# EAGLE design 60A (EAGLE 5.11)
PID: 626
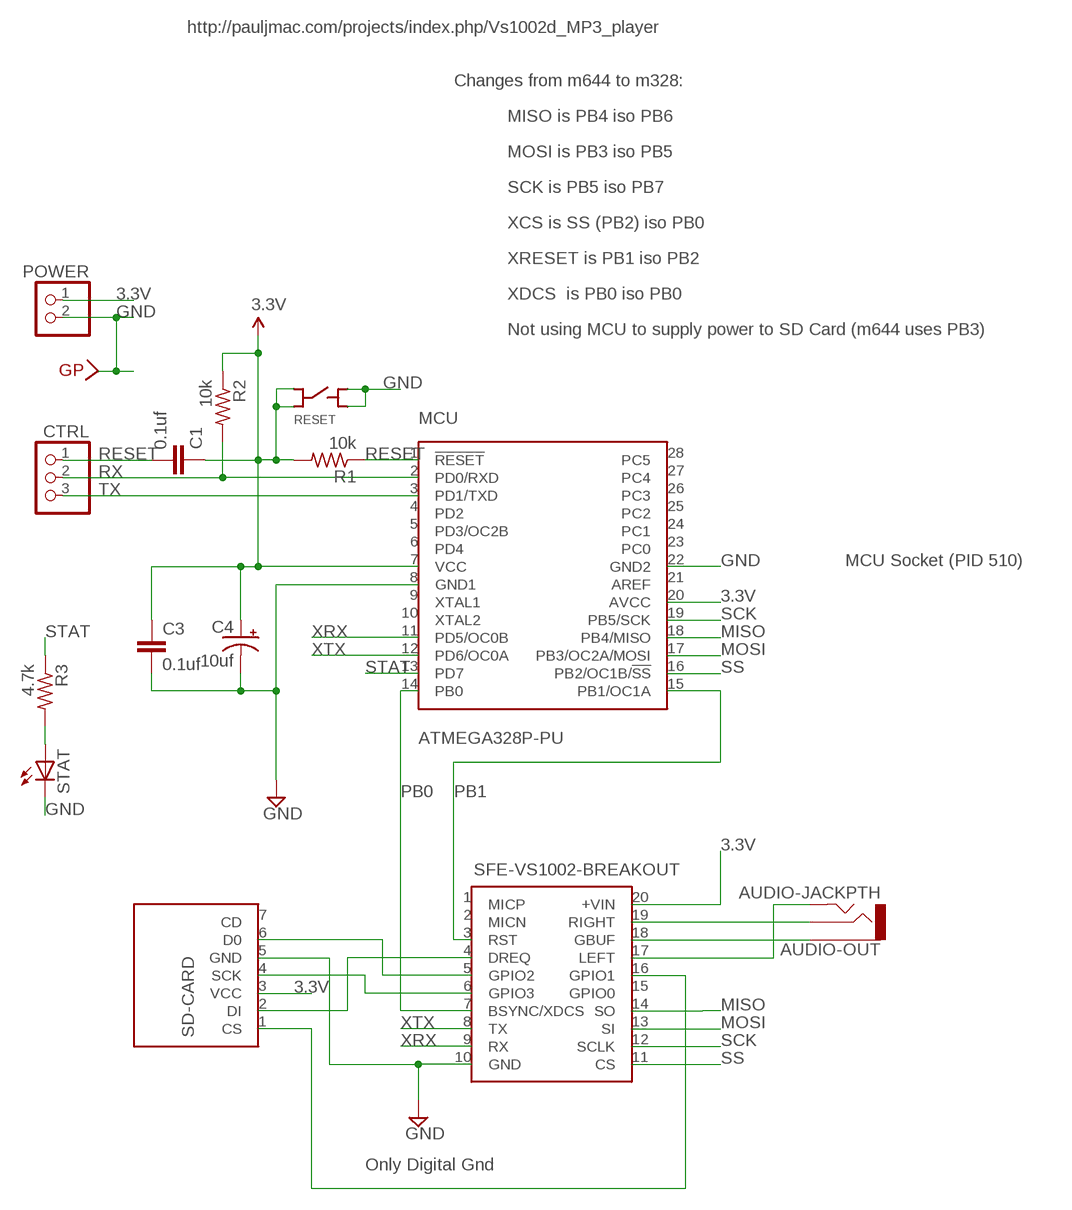
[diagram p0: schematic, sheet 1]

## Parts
AUDIO-OUT  AUDIO-JACKPTH  [AUDIO-JACK]
C1  0.1uf  C-EUC1206  [C1206]
C3  0.1uf  C-EUC1206  [C1206]
C4  10uf  CPOL-USE2-4  [E2-4]
CTRL  PINHD-1X3  [1X03]
GP  WIREPAD-SMD-SMALL-NAMED  [WIREPAD-SMD-SMALL]
MCU  ATMEGA328P-PU  [DIL28-3]
POWER  PINHD-1X2  [1X02]
R1  10k  R-US_M0805  [M0805]
R2  10k  R-US_R0805  [R0805]
R3  4.7k  R-US_R1206  [R1206]
RESET  SFE-PUSHBUTTON-SWITCH  [SFE-PUSHBUTTON-SWITCH]
SD-CARD  SFE-MICRO-SD-CARD-BREAKOUT  [SFE-MICRO-SD-CARD-BREAKOUT]
SFE-VS1002-BREAKOUT  SFE-VS1002-BREAKOUT  [SFE-VS1002-BREAKOUT]
STAT  LED5MM  [LED5MM]

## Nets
3.3V: C1.1 C3.1 C4.+ MCU.7(VCC) MCU.20(AVCC) POWER.1 R1.2 R2.1 RESET.C@1(C) RESET.C@2(C) SD-CARD.3(VCC) SFE-VS1002-BREAKOUT.20(+VIN)
GND: C3.2 C4.- GP.1 MCU.8(GND1) MCU.22(GND2) POWER.2 RESET.O@1(O) RESET.O@2(O) SD-CARD.5(GND) SFE-VS1002-BREAKOUT.10(GND) STAT.K(C)
MISO: MCU.18(PB4/MISO) SFE-VS1002-BREAKOUT.14(SO)
MOSI: MCU.17(PB3/OC2A/MOSI) SFE-VS1002-BREAKOUT.13(SI)
N$1: R3.2 STAT.A
N$2: AUDIO-OUT.1 SFE-VS1002-BREAKOUT.18(GBUF)
N$3: AUDIO-OUT.2 SFE-VS1002-BREAKOUT.19(RIGHT)
N$4: SD-CARD.2(DI) SFE-VS1002-BREAKOUT.4(DREQ)
N$5: SD-CARD.4(SCK) SFE-VS1002-BREAKOUT.6(GPIO3)
N$6: SD-CARD.6(D0) SFE-VS1002-BREAKOUT.5(GPIO2)
N$7: SD-CARD.1(CS) SFE-VS1002-BREAKOUT.16(GPIO1)
N$8: AUDIO-OUT.5 SFE-VS1002-BREAKOUT.17(LEFT)
PB0: MCU.14(PB0) SFE-VS1002-BREAKOUT.7(BSYNC/XDCS)
PB1: MCU.15(PB1/OC1A) SFE-VS1002-BREAKOUT.3(RST)
RESET: C1.2 CTRL.1 MCU.1(!RESET) R1.1
RX: CTRL.2 MCU.2(PD0/RXD) R2.2
SCK: MCU.19(PB5/SCK) SFE-VS1002-BREAKOUT.12(SCLK)
SS: MCU.16(PB2/OC1B/!SS) SFE-VS1002-BREAKOUT.11(CS)
STAT: MCU.13(PD7) R3.1
TX: CTRL.3 MCU.3(PD1/TXD)
XRX: MCU.11(PD5/OC0B) SFE-VS1002-BREAKOUT.9(RX)
XTX: MCU.12(PD6/OC0A) SFE-VS1002-BREAKOUT.8(TX)
Unconnected: MCU.4(PD2) MCU.5(PD3/OC2B) MCU.6(PD4) MCU.9(XTAL1) MCU.10(XTAL2) MCU.21(AREF) MCU.23(PC0) MCU.24(PC1) MCU.25(PC2) MCU.26(PC3) MCU.27(PC4) MCU.28(PC5) SD-CARD.7(CD) SFE-VS1002-BREAKOUT.1(MICP) SFE-VS1002-BREAKOUT.2(MICN) SFE-VS1002-BREAKOUT.15(GPIO0)

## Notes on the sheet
- http://pauljmac.com/projects/index.php/Vs1002d_MP3_player
- Changes from m644 to m328:
- MISO is PB4 iso PB6
- MOSI is PB3 iso PB5
- SCK is PB5 iso PB7
- XCS is SS (PB2) iso PB0
- XRESET is PB1 iso PB2
- XDCS  is PB0 iso PB0
- Not using MCU to supply power to SD Card (m644 uses PB3)
- MCU Socket (PID 510)
- Only Digital Gnd

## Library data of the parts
AUDIO-OUT = SparkFun:AUDIO-JACK: 3.5mm Audio Jack Simple 3.5mm common PCB mount audio jack. SKU: PRT-08032
C1 C3 = rcl:C-EU: CAPACITOR, European symbol
C4 = rcl:CPOL-US: POLARIZED CAPACITOR, American symbol
CTRL = pinhead:PINHD-1X3: PIN HEADER
GP = trl:WIREPAD-SMD-SMALL-NAMED
MCU = trl:ATMEGA328P-PU
POWER = pinhead:PINHD-1X2: PIN HEADER
R1-R3 = resistor:R-US_: RESISTOR, American symbol
RESET = trl:SFE-PUSHBUTTON-SWITCH
SD-CARD = trl:SFE-MICRO-SD-CARD-BREAKOUT
SFE-VS1002-BREAKOUT = trl:SFE-VS1002-BREAKOUT
STAT = led:LED: LED

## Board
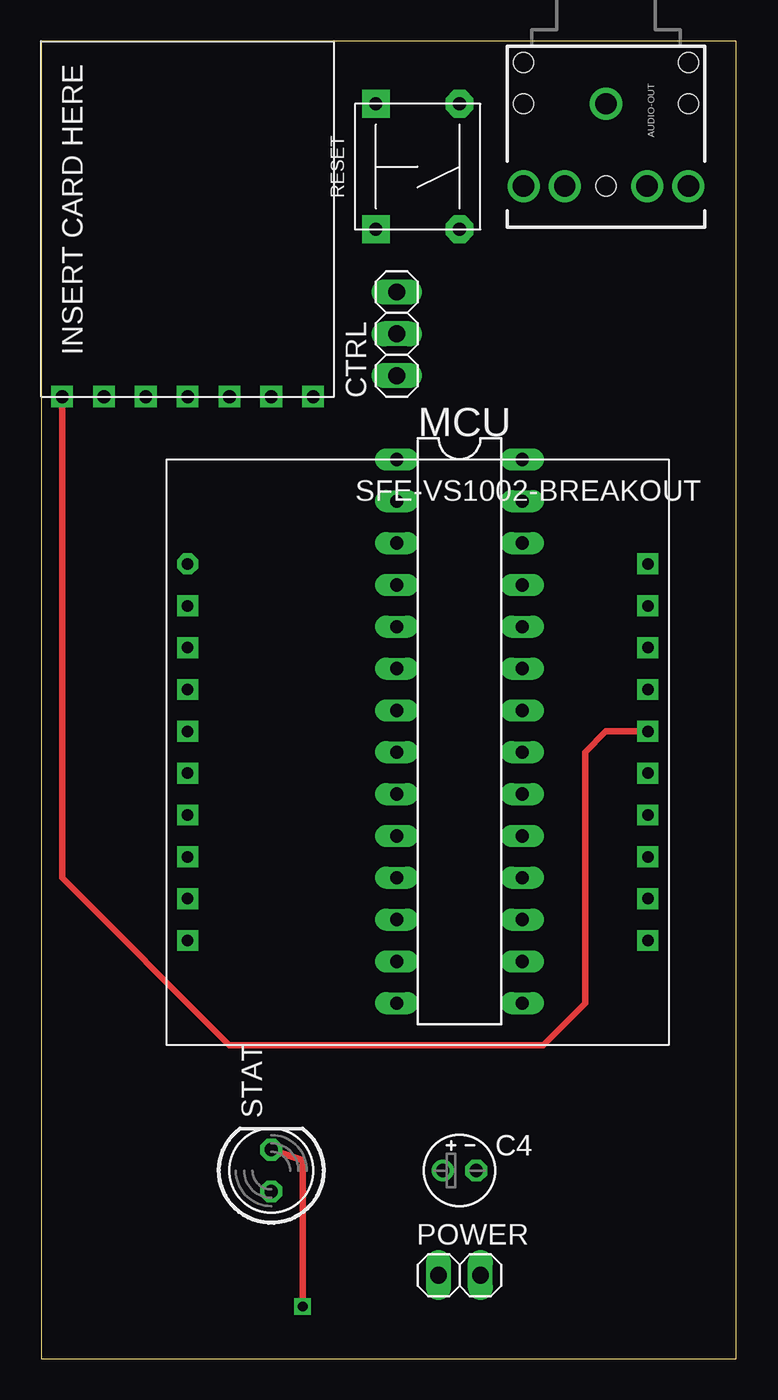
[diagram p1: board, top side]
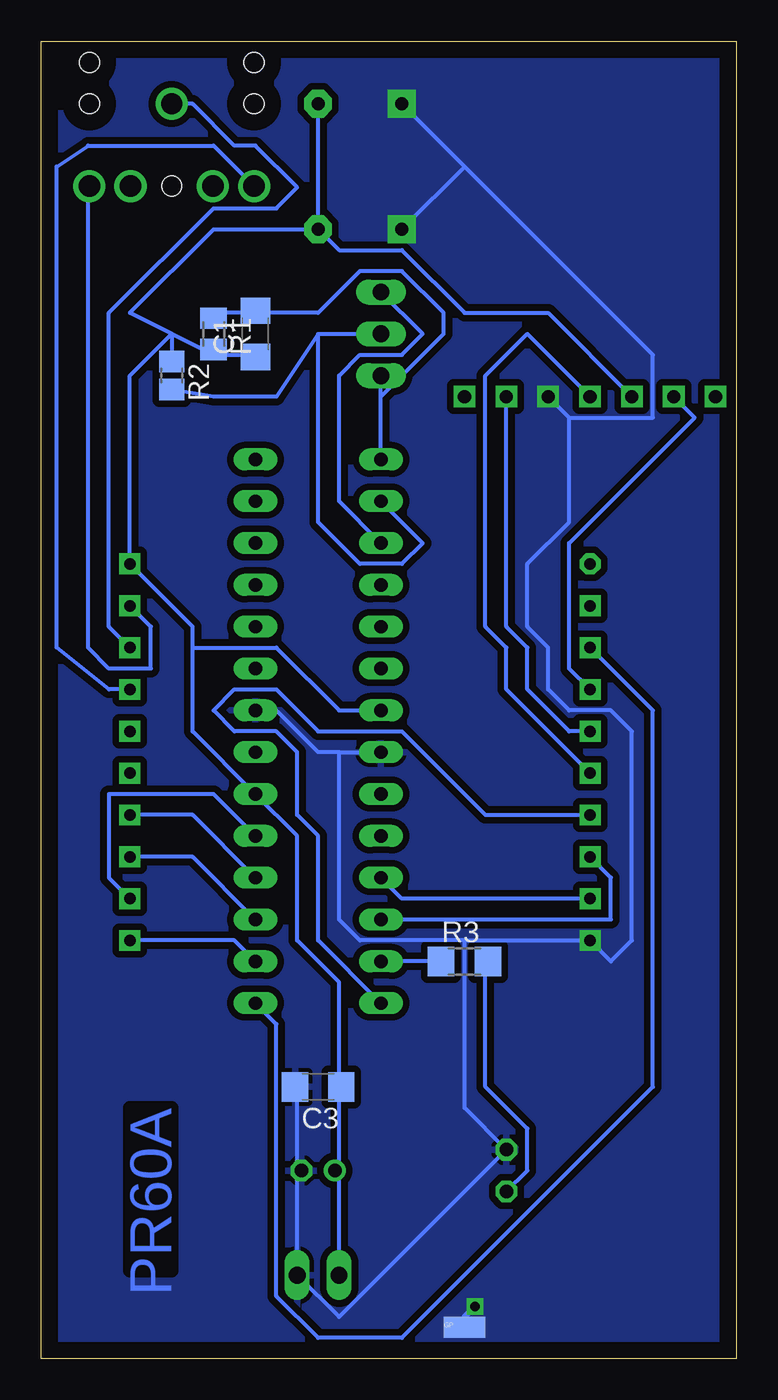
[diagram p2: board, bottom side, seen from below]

Size 42.22 x 80 mm. Coordinates in mm from the lower left corner, seen from the top.
Outline: 0,0 42.22,0 42.22,80 0,80 0,0
Copper layers (1*16): Top 0.035mm / dielectric 1.5mm / Bottom 0.035mm
Design rules "default": minimum track width 10mil, minimum drill 24mil, track to track 8mil, track to pad 8mil, pad to pad 8mil, via to via 8mil, smd to smd 8mil, copper to edge 40mil, drill to drill 8mil, minimum pad ring 10mil, minimum via ring 8mil, stop-mask expansion 4mil, vias tented up to drill 0mil, thermal gap 10mil

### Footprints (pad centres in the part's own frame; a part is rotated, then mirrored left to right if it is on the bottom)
AUDIO-JACK = drill 1.3 round: 1 0,0; 2 5,5; 3 5,2.5; 4 5,-2.5; 5 5,-5 | hole 1.2: 0,5; -2.5,5; -2.5,-5; 0,-5; 5,0
C1206 = smd 1.6 x 1.8: 1 -1.4,0; 2 1.4,0
E2-4 = drill 0.813 pad 1.27 round: + -1.016,0 | drill 0.813 pad 1.27 octagon: - 1.016,0
1X03 = drill 1.016 long: 1 -2.54,0; 2 0,0; 3 2.54,0
WIREPAD-SMD-SMALL = smd 2.54 x 1.27: 1 0,0
DIL28-3 = drill 0.813 long: 1 -16.51,-3.81; 2 -13.97,-3.81; 3 -11.43,-3.81; 4 -8.89,-3.81; 5 -6.35,-3.81; 6 -3.81,-3.81; 7 -1.27,-3.81; 8 1.27,-3.81; 9 3.81,-3.81; 10 6.35,-3.81; 11 8.89,-3.81; 12 11.43,-3.81; 13 13.97,-3.81; 14 16.51,-3.81; 15 16.51,3.81; 16 13.97,3.81; 17 11.43,3.81; 18 8.89,3.81; 19 6.35,3.81; 20 3.81,3.81; 21 1.27,3.81; 22 -1.27,3.81; 23 -3.81,3.81; 24 -6.35,3.81; 25 -8.89,3.81; 26 -11.43,3.81; 27 -13.97,3.81; 28 -16.51,3.81
1X02 = drill 1.016 long: 1 -1.27,0; 2 1.27,0
M0805 = smd 1.3 x 1.6: 1 -0.95,0; 2 0.95,0
R0805 = smd 1.3 x 1.5: 1 -0.85,0; 2 0.85,0
R1206 = smd 1.6 x 1.803: 1 -1.422,0; 2 1.422,0
SFE-PUSHBUTTON-SWITCH = drill 0.8 pad 1.676 octagon: C@1 -3.81,-2.54; C@2 3.81,-2.54 | drill 0.8 pad 1.676 square: O@1 -3.81,2.54; O@2 3.81,2.54
SFE-MICRO-SD-CARD-BREAKOUT = drill 0.8 square: 1 -7.62,-10.16; 2 -5.08,-10.16; 3 -2.54,-10.16; 4 0,-10.16; 5 2.54,-10.16; 6 5.08,-10.16; 7 7.62,-10.16
SFE-VS1002-BREAKOUT = drill 0.7 pad 1.27 octagon: 1 -13.97,11.43 | drill 0.7 pad 1.27 square: 2 -13.97,8.89; 3 -13.97,6.35; 4 -13.97,3.81; 5 -13.97,1.27; 6 -13.97,-1.27; 7 -13.97,-3.81; 8 -13.97,-6.35; 9 -13.97,-8.89; 10 -13.97,-11.43; 11 13.97,-11.43; 12 13.97,-8.89; 13 13.97,-6.35; 14 13.97,-3.81; 15 13.97,-1.27; 16 13.97,1.27; 17 13.97,3.81; 18 13.97,6.35; 19 13.97,8.89; 20 13.97,11.43
LED5MM = drill 0.813 octagon: A -1.27,0; K 1.27,0

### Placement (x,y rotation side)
AUDIO-OUT  34.29,76.2 270 top
C1  29.21,62.23 90 bottom
C3  25.4,16.51 180 bottom
C4  25.4,11.43 0 top
CTRL  21.59,62.23 90 top
GP  16.51,1.91 0 bottom
MCU  25.4,38.1 270 top
POWER  25.4,5.08 0 top
R1  31.75,62.23 270 bottom
R2  34.29,59.69 270 bottom
R3  16.51,24.13 0 bottom
RESET  22.86,72.39 90 top
SD-CARD  8.89,68.58 0 top
SFE-VS1002-BREAKOUT  22.86,36.83 0 top
STAT  13.97,11.43 90 top

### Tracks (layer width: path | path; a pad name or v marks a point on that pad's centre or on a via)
3.3V
  Bottom 0.254: SD-CARD.3 11.43,63.5 16.51,63.5 20.32,67.31 24.13,67.31 RESET.C@1 | RESET.C@1 RESET.C@2 | 24.13,11.43 24.13,16.51 | POWER.1 24.13,11.43 | 24.13,11.43 C4.+ | 31.75,60.96 29.21,60.96 C1.1 | 34.29,62.23 31.75,60.96 | 31.75,60.96 R1.2 | 34.29,62.23 36.83,59.69 SFE-VS1002-BREAKOUT.20 33.02,44.45 33.02,43.18 | 33.02,43.18 33.02,38.1 MCU.20 26.67,31.75 26.67,25.4 24.13,22.86 24.13,16.51 | MCU.7 24.13,39.37 27.94,43.18 33.02,43.18 | 24.13,16.51 C3.1 | RESET.C@1 31.75,68.58 36.83,63.5 34.29,62.23 | 34.29,62.23 R2.1
GND  (via drill 0.6)
  Top 0.406: v15.88,3.17 15.88,12.06 STAT.K
  Bottom 0.254: 10.16,57.15 SD-CARD.5 | 10.16,57.15 5.08,57.15 5.08,60.96 16.51,72.39 | 16.51,72.39 RESET.O@2 | 16.51,72.39 RESET.O@1 | 26.67,11.43 26.67,16.51 C3.2 | 26.67,11.43 POWER.2 24.13,2.54 STAT.K 16.51,15.24 16.51,25.4 | 26.67,11.43 C4.- | 24.13,36.83 25.4,36.83 27.94,39.37 MCU.22 | 24.13,36.83 MCU.8 | 16.51,25.4 SFE-VS1002-BREAKOUT.10 7.62,24.13 6.35,25.4 6.35,38.1 7.62,39.37 10.16,39.37 11.43,40.64 11.43,43.18 12.7,44.45 12.7,48.26 10.16,50.8 10.16,57.15 | 24.13,36.83 24.13,26.67 22.86,25.4 16.51,25.4
  Bottom 0.406: GP.1 16.51,2.54 v15.88,3.17
  pour Bottom (isolate 0.406): 0,80.01 41.91,80.01 41.91,78.74 41.91,0 0,0
MISO
  Bottom 0.254: SFE-VS1002-BREAKOUT.14 33.02,33.02 MCU.18
MOSI
  Bottom 0.254: SFE-VS1002-BREAKOUT.13 33.02,30.48 MCU.17
N$1
  Bottom 0.254: STAT.A 12.7,11.43 12.7,13.97 15.24,16.51 15.24,24.13 R3.2
N$2
  Bottom 0.254: SFE-VS1002-BREAKOUT.18 38.1,44.45 38.1,63.5 31.75,69.85 27.94,69.85 26.67,71.12 29.21,73.66 30.48,73.66 33.02,76.2 AUDIO-OUT.1
N$3
  Bottom 0.254: SFE-VS1002-BREAKOUT.19 35.56,44.45 35.56,41.91 38.1,41.91 39.37,43.18 39.37,71.12 AUDIO-OUT.2
N$4
  Bottom 0.254: SFE-VS1002-BREAKOUT.4 10.16,41.91 10.16,49.53 2.54,57.15 SD-CARD.2
N$5
  Bottom 0.254: SFE-VS1002-BREAKOUT.6 13.97,40.64 13.97,43.18 15.24,44.45 15.24,59.69 12.7,62.23 SD-CARD.4
N$6
  Bottom 0.254: SFE-VS1002-BREAKOUT.5 10.16,38.1 12.7,40.64 12.7,43.18 13.97,44.45 SD-CARD.6
N$7
  Top 0.406: SD-CARD.1 1.27,29.21 11.43,19.05 30.48,19.05 33.02,21.59 33.02,36.83 34.29,38.1 SFE-VS1002-BREAKOUT.16
N$8
  Bottom 0.254: SFE-VS1002-BREAKOUT.17 38.1,40.64 41.27,43.18 41.27,72.39 39.37,73.66 31.75,73.66 AUDIO-OUT.5 29.21,71.12
PB0
  Bottom 0.254: SFE-VS1002-BREAKOUT.7 15.24,33.02 20.32,38.1 25.4,38.1 27.94,40.64 30.48,40.64 31.75,39.37 30.48,38.1 27.94,38.1 26.67,36.83 26.67,33.02 25.4,31.75 25.4,25.4 MCU.14
PB1
  Bottom 0.254: SFE-VS1002-BREAKOUT.3 5.08,39.37 5.08,16.51 20.32,1.27 25.4,1.27 27.94,3.81 27.94,20.32 MCU.15
RESET
  Bottom 0.254: 29.21,63.5 31.75,63.5 R1.1 | 21.59,58.42 CTRL.1 | MCU.1 21.59,58.42 | 29.21,63.5 25.4,63.5 22.86,66.04 20.32,66.04 17.78,63.5 17.78,62.23 21.59,58.42 | 29.21,63.5 C1.2
RX
  Bottom 0.254: 25.4,62.23 CTRL.2 | 25.4,62.23 27.94,58.42 31.75,58.42 R2.2 | MCU.2 19.05,49.53 20.32,48.26 22.86,48.26 25.4,50.8 25.4,62.23
SCK
  Bottom 0.254: SFE-VS1002-BREAKOUT.12 38.1,29.21 38.1,34.29 31.75,34.29 MCU.19
SS
  Bottom 0.254: SFE-VS1002-BREAKOUT.11 30.48,25.4 MCU.16
STAT
  Bottom 0.254: MCU.13 R3.1 17.78,24.13
TX
  Bottom 0.254: MCU.3 24.13,52.07 24.13,59.69 22.86,60.96 20.32,60.96 19.05,62.23 CTRL.3
XRX
  Bottom 0.254: SFE-VS1002-BREAKOUT.9 20.32,27.94 MCU.11
XTX
  Bottom 0.254: SFE-VS1002-BREAKOUT.8 7.62,29.21 7.62,26.67 MCU.12

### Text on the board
Bottom: PR60A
